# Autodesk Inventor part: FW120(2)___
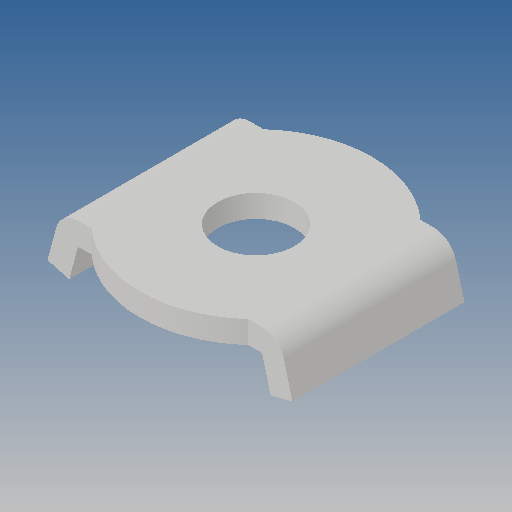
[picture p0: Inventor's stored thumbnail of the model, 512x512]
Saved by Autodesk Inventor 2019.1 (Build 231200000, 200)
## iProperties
Created: 2010-06
Part Number: FW120(2)___
Material: Ogólny
Document SubType Name: Modeling
Designer: CADENGINEERING4
Density: 1 g/cm^3
Appearance: Domyślna
Author: CADENGINEERING4
Revision Number: ANY
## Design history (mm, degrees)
feature "NONE"
node "Bryła1"
